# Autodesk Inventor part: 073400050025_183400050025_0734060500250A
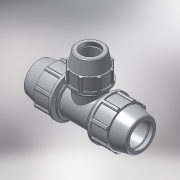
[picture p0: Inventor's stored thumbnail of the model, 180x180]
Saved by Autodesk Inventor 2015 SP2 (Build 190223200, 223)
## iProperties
Created: 2017-02
Part Number: 073400050025_183400050025_0734060500250A
Material: PVC-Piping
Description: PLASSON REDUCING TEE 50-25-50
Document SubType Name: Modeling
Designer: KIM
Mass: 92.6774 g
Surface Area: 199.44 cm^2
Volume: 66.1981 cm^3
Density: 1.4 g/cm^3
Appearance: Smooth - White
Author: Кирилл
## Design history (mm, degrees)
derived "07340.ipt"
feature "Solid1::07340.ipt"
feature "Solid2::07340.ipt"
tag "TaggingFeature1"
body "Solid1"
other parameters: "d4" = 9.5, "d5" = 31.92, "d7" = 96, "d11" = 3.8, "d13" = 120 deg, "d15" = 12 deg, "d16" = 83.52, "d18" = 2.5, "d19" = 35 deg, "d20" = 17.5 deg, "d21" = 89.28, "d23" = 0, "d25" = 360 deg, "d27" = 1.92, "d33" = 1, "d42" = 41.04, "d43" = 2.88, "d46" = 1.5, "d67" = 72, "d76" = 25, "d77" = 54, "d78" = 12 deg, "d79" = 105, "d80" = 120 deg, "d81" = 37.5, "d82" = 8.75, "d87" = 3.5, "d89" = 26.25, "d90" = 31.5, "d96" = 19, "d98" = 50.22, "d99" = 35 deg, "d100" = 17.5 deg, "d102" = 0, "d103" = 1.08, "d107" = 360 deg, "d109" = 0.75, "d112" = 1.25, "d113" = 3.6, "d114" = 0, "d117" = 228, "d118" = 46.98, "d126" = 45, "d127" = 93, "d131" = 4.2, "d132" = 22.5, "d133" = 76, "d135" = 0, "d138" = 4.56, "d143" = 0, "d148" = 40.5, "d168" = 45, "d170" = 0, "d171" = 25, "d173" = 0, "d175" = 0, "d176" = 3.6, "d177" = 0, "E_" = 96, "A_" = 105, "l_" = 93, "E_1" = 54, "l_1" = 76, "d_1" = 25, "H_" = 228
